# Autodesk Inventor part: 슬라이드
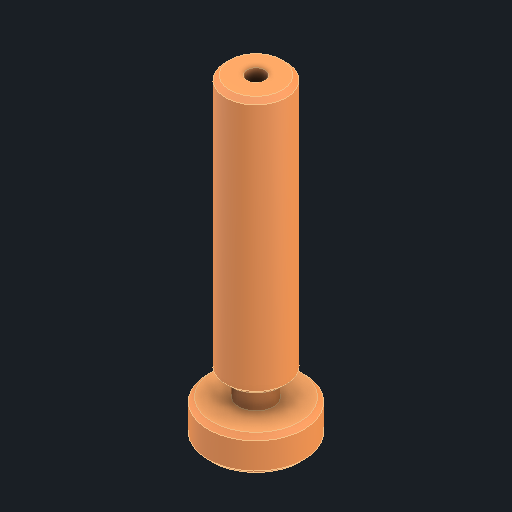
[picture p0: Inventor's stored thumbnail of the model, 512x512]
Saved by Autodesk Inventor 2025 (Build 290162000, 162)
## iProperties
Created: 2025-08
Part Number: 슬라이드
Material: 강철, 연강
Document SubType Name: Modeling
Designer: infra14
Density: 7.86 g/cm^3
Appearance: 기본값
Author: jhkim
Sending System: Autodesk Inventor 2026
Preprocessor: ST-DEVELOPER v20.1
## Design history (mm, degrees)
feature "솔리드1"
node "솔리드2"
